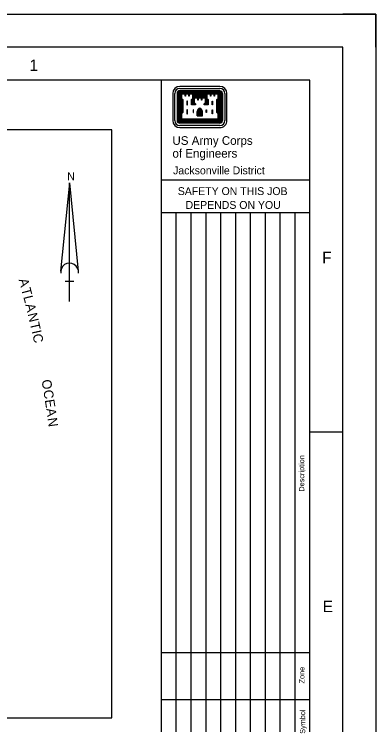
# Model space of a CAD drawing. Extents: x 464090 to 640095, y 2137521 to 2273520.
# Drawn here: x 618182 to 640089, y 2230445 to 2273520 of the extents above; entities that cross this region are included whole.
import ezdxf

# ---------------------------------------------------------------- set-up
doc = ezdxf.new("R2010")
doc.units = 0
for name, color, linetype in [('G-ANNO-NPLT', 7, 'Continuous'), ('G-ANNO-TEXT-LOGO', 7, 'Continuous'), ('G-ANNO-TEXT-TTLB', 7, 'Continuous'), ('G-ANNO-TTLB', 7, 'Continuous'), ('V-ANNO-SYMB', 7, 'Continuous')]:
    doc.layers.add(name, color=color, linetype=linetype)

msp = doc.modelspace()

# ---------------------------------------------------------------- linework, layer by layer
at = {"layer": 'G-ANNO-NPLT'}
msp.add_lwpolyline([(464090, 2273520), (640089, 2273520), (640089, 2137521), (464090, 2137521)], close=True, dxfattribs=at)
msp.add_lwpolyline([(640089, 2271520), (640089, 2273520), (638089, 2273520)], dxfattribs=at)
at = {"layer": 'G-ANNO-TEXT-LOGO'}
for p, q in [((630644, 2269145), (628212, 2269145)), ((628212, 2269017), (630644, 2269017)), ((630644, 2268881), (628212, 2268881)), ((630644, 2268845), (628212, 2268845)), ((630644, 2268809), (628212, 2268809)), ((630644, 2268777), (628212, 2268777)), ((627784, 2268717), (627784, 2267077)), ((627912, 2267077), (627912, 2268717)), ((628052, 2268717), (628052, 2267077)), ((628088, 2268717), (628088, 2267077)), ((628120, 2268717), (628120, 2267077)), ((628156, 2268717), (628156, 2267077)), ((628192, 2268717), (628192, 2267077)), ((630644, 2268741), (628212, 2268741)), ((628228, 2268717), (628228, 2267089)), ((628260, 2268717), (628260, 2267125)), ((628288, 2268369), (628288, 2267529)), ((628324, 2268333), (628324, 2267569)), ((629056, 2268709), (629800, 2268709)), ((629056, 2268673), (629800, 2268673)), ((629056, 2268641), (629800, 2268641)), ((629056, 2268605), (629800, 2268605)), ((629056, 2268569), (629800, 2268569)), ((629056, 2268537), (629800, 2268537)), ((629056, 2268501), (629800, 2268501)), ((630532, 2268333), (630532, 2267569)), ((630568, 2268365), (630568, 2267533)), ((630596, 2268717), (630596, 2267125)), ((630628, 2268717), (630628, 2267089)), ((630664, 2268717), (630664, 2267077)), ((630700, 2268717), (630700, 2267077)), ((630732, 2268717), (630732, 2267077)), ((630768, 2268717), (630768, 2267077)), ((630804, 2268717), (630804, 2267077)), ((630940, 2268717), (630940, 2267077)), ((631072, 2267077), (631072, 2268717)), ((629268, 2267361), (629268, 2267629)), ((629300, 2267361), (629300, 2267629)), ((629336, 2267361), (629336, 2267629)), ((629372, 2267361), (629372, 2267629)), ((629404, 2267361), (629404, 2267629)), ((629452, 2267361), (629452, 2267629)), ((629484, 2267361), (629484, 2267629)), ((629520, 2267361), (629520, 2267629)), ((629556, 2267361), (629556, 2267629)), ((629588, 2267361), (629588, 2267629)), ((630644, 2267053), (628212, 2267053)), ((630628, 2267089), (628228, 2267089)), ((630596, 2267125), (628260, 2267125)), ((629268, 2267361), (629588, 2267361)), ((630644, 2267021), (628212, 2267021)), ((630644, 2266985), (628212, 2266985)), ((630644, 2266949), (628212, 2266949)), ((630644, 2266917), (628212, 2266917)), ((630644, 2266777), (628212, 2266777)), ((628212, 2266645), (630644, 2266645))]:
    msp.add_line(p, q, dxfattribs=at)
for points in [[(628288, 2268717), (628288, 2268401), (628356, 2268333), (628356, 2267569), (628288, 2267497), (628288, 2267149), (630568, 2267149), (630568, 2267497), (630496, 2267569), (630496, 2268333), (630568, 2268401), (630568, 2268717), (630268, 2268717), (630036, 2268717), (629820, 2268717), (629820, 2268401), (629896, 2268333), (629896, 2268053), (629728, 2268053), (629728, 2268081), (629800, 2268153), (629800, 2268465), (629500, 2268465), (629268, 2268465), (629056, 2268465), (629056, 2268153), (629128, 2268081), (629128, 2268053), (628960, 2268053), (628960, 2268333), (629032, 2268401), (629032, 2268717), (628732, 2268717), (628500, 2268717), (628288, 2268717)], [(628320, 2268681), (628320, 2268417), (628392, 2268345), (628392, 2267553), (628320, 2267481), (628320, 2267185), (630536, 2267185), (630536, 2267481), (630460, 2267553), (630460, 2268345), (630536, 2268417), (630536, 2268681), (630320, 2268681), (630320, 2268557), (630300, 2268557), (630300, 2268681), (630088, 2268681), (630088, 2268557), (630072, 2268557), (630072, 2268681), (629856, 2268681), (629856, 2268417), (629928, 2268345), (629928, 2268021), (629696, 2268021), (629696, 2268097), (629768, 2268169), (629768, 2268433), (629552, 2268433), (629552, 2268309), (629536, 2268309), (629536, 2268433), (629320, 2268433), (629320, 2268309), (629300, 2268309), (629300, 2268433), (629088, 2268433), (629088, 2268169), (629160, 2268097), (629160, 2268021), (628928, 2268021), (628928, 2268345), (629000, 2268417), (629000, 2268681), (628788, 2268681), (628788, 2268557), (628768, 2268557), (628768, 2268681), (628552, 2268681), (628552, 2268557), (628536, 2268557), (628536, 2268681), (628320, 2268681)], [(629016, 2268337), (628996, 2268317), (628996, 2268089), (629072, 2268089), (629020, 2268141), (629020, 2268341)], [(629840, 2268337), (629860, 2268317), (629860, 2268089), (629788, 2268089), (629836, 2268141), (629836, 2268341)], [(628648, 2268253), (628648, 2268021), (628672, 2268021), (628672, 2268253), (628648, 2268253)], [(630204, 2268253), (630204, 2268021), (630184, 2268021), (630184, 2268253), (630204, 2268253)], [(628648, 2267721), (628648, 2267485), (628672, 2267485), (628672, 2267721), (628648, 2267721)], [(629016, 2267721), (629016, 2267557), (629036, 2267557), (629036, 2267721), (629016, 2267721)], [(629840, 2267721), (629840, 2267557), (629820, 2267557), (629820, 2267721), (629840, 2267721)], [(630204, 2267721), (630204, 2267485), (630184, 2267485), (630184, 2267721), (630204, 2267721)]]:
    msp.add_lwpolyline(points, dxfattribs=at)
for centre, major_axis, start_param, end_param in [((628213, 2268718), (429, 0), 1.57078, 3.141576), ((628213, 2268718), (300, 0), 1.57078, 3.141576), ((628213, 2268718), (161, 0), 1.57078, 3.141576), ((628213, 2268718), (126, 0), 1.57078, 3.141576), ((628213, 2268718), (91.3, 0), 1.57078, 3.141576), ((628213, 2268718), (56.5, 0), 1.57078, 3.141576), ((630641, 2268717), (429, 0), 6.283169, 7.853965), ((630641, 2268717), (300, 0), 6.28317, 7.853966), ((630641, 2268717), (161, 0), 6.283169, 7.853965), ((630641, 2268717), (126, 0), 6.283169, 7.853965), ((630641, 2268717), (91.3, 0), 6.283169, 7.853965), ((630641, 2268717), (56.5, 0), 6.283169, 7.853965), ((628213, 2268718), (21.8, 0), 1.57078, 3.141576), ((630641, 2268717), (21.8, 0), 6.283169, 7.853965), ((629487, 2267611), (-222, 0), 4.985832, 6.214359), ((629487, 2267611), (-187, 0), 4.947465, 6.21436), ((629487, 2267611), (-153, 0), 4.947465, 6.21436), ((629487, 2267611), (-118, 0), 4.947465, 6.21436), ((629367, 2267611), (83.3, 0), 0.068794, 1.335689), ((629367, 2267611), (118, 0), 0.068794, 1.335689), ((629367, 2267611), (153, 0), 0.068795, 1.335689), ((629487, 2267611), (-83.3, 0), 4.947465, 6.214359), ((629367, 2267611), (187, 0), 0.068795, 1.335689), ((629367, 2267611), (222, 0), 0.068795, 1.29842), ((628213, 2267075), (-429, 0), 6.28317, 7.853966), ((628213, 2267075), (-300, 0), 6.28317, 7.853966), ((628213, 2267075), (-161, 0), 6.28317, 7.853966), ((628213, 2267075), (-126, 0), 6.28317, 7.853966), ((628213, 2267075), (-91.3, 0), 6.28317, 7.853966), ((628213, 2267075), (-56.5, 0), 6.28317, 7.853966), ((628213, 2267075), (-21.8, 0), 6.28317, 7.853966), ((630641, 2267075), (161, 0), 4.712373, 6.28317), ((630641, 2267075), (126, 0), 4.712373, 6.28317), ((630641, 2267075), (91.3, 0), 4.712373, 6.28317), ((630641, 2267075), (56.5, 0), 4.712373, 6.28317), ((630641, 2267075), (21.8, 0), 4.712373, 6.28317), ((630641, 2267075), (429, 0), 4.712373, 6.28317), ((630641, 2267075), (-300, 0), 1.570781, 3.141577)]:
    msp.add_ellipse(centre, major_axis=major_axis, ratio=0.99964, start_param=start_param, end_param=end_param, dxfattribs=at)
at = {"layer": 'G-ANNO-TTLB'}
for p, q in [((627088, 2269520), (627088, 2141521)), ((627089, 2263471), (636089, 2263471)), ((627065, 2261506), (636065, 2261506)), ((627982, 2261506), (627982, 2227990)), ((628882, 2261506), (628882, 2227990)), ((629782, 2261506), (629782, 2227990)), ((630682, 2261506), (630682, 2227990)), ((631582, 2261506), (631582, 2227990)), ((632482, 2261506), (632482, 2227990)), ((633382, 2261506), (633382, 2227990)), ((634282, 2261506), (634282, 2227990)), ((635182, 2261506), (635182, 2227990)), ((638089, 2248180), (636089, 2248180)), ((627089, 2234831), (636089, 2234831)), ((627089, 2231984), (636089, 2231984))]:
    msp.add_line(p, q, dxfattribs=at)
for points in [[(466090, 2139521), (638089, 2139521), (638089, 2271520), (466090, 2271520)], [(636089, 2269520), (471090, 2269520), (471090, 2141521), (636089, 2141521)]]:
    msp.add_lwpolyline(points, close=True, dxfattribs=at)
at = {"layer": 'V-ANNO-SYMB'}
for p, q in [((624088, 2266520), (584575, 2266520)), ((624088, 2230868), (624088, 2266520)), ((620998, 2257951), (621554, 2263293)), ((621535, 2256095), (621535, 2263295)), ((622073, 2257947), (621551, 2263297)), ((621263, 2257336), (621803, 2257336)), ((584575, 2230868), (624088, 2230868))]:
    msp.add_line(p, q, dxfattribs=at)
msp.add_arc((621535, 2257895), 540, 353.3459, 188.7908, dxfattribs=at)

# ---------------------------------------------------------------- texts
at = {"layer": 'G-ANNO-TEXT-TTLB'}
for s, height, p in [('US Army Corps', 523.44, (627768, 2265601)), ('of Engineers', 523.44, (627768, 2264825)), ('Jacksonville District', 475.99, (627808, 2263813)), ('SAFETY ON THIS JOB', 476, (628093, 2262557)), ('DEPENDS ON YOU', 476, (628564, 2261721))]:
    msp.add_text(s, height=height, dxfattribs=at).set_placement(p)
for s, p in [('Description', (635754, 2244579)), ('Zone', (635766, 2232951)), ('Symbol', (635813, 2229898))]:
    msp.add_text(s, height=320, rotation=90, dxfattribs=at).set_placement(p)
at = {"layer": 'G-ANNO-TTLB'}
for s, p in [('1', (619106, 2270074)), ('F', (636841, 2258427)), ('E', (636872, 2237274))]:
    msp.add_text(s, height=700, dxfattribs=at).set_placement(p)
at = {"layer": 'V-ANNO-SYMB'}
for s, height, rotation, p in [('N', 472, 0, (621398, 2263454)), ('A', 576, 285.3188, (618449, 2257423)), ('T', 576, 284.8034, (618602, 2256863)), ('L', 576, 284.3674, (618728, 2256387)), ('A', 576, 283.9315, (618851, 2255911)), ('N', 576, 283.4161, (618991, 2255347)), ('T', 576, 282.9008, (619125, 2254782)), ('I', 576, 282.4648, (619236, 2254302)), ('C', 576, 282.2667, (619284, 2254084)), ('O', 576, 279.7701, (619835, 2251323)), ('C', 576, 279.215, (619941, 2250706)), ('E', 576, 278.6996, (620034, 2250132)), ('A', 576, 278.2236, (620116, 2249601)), ('N', 576, 277.7082, (620199, 2249026))]:
    msp.add_text(s, height=height, rotation=rotation, dxfattribs=at).set_placement(p)

doc.saveas('drawing.dxf')
